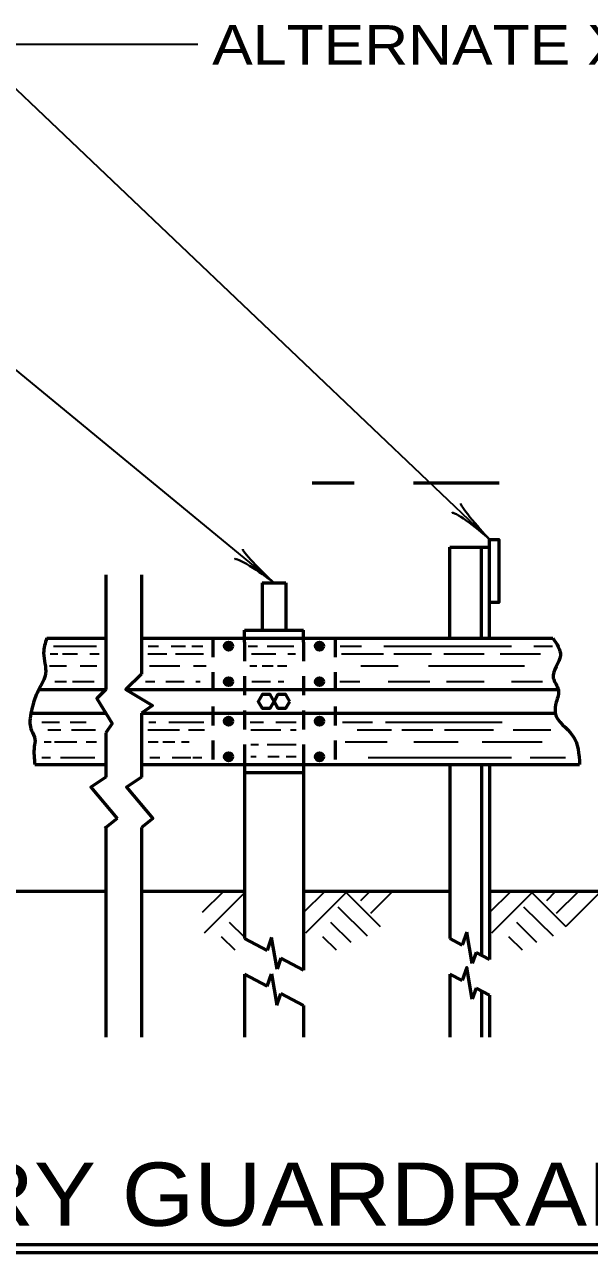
# Model space of a CAD drawing. Extents: x -60 to 620, y -42 to 398.
# Drawn here: x 228.6 to 264.3, y 75.7 to 153.4 of the extents above; entities that cross this region are included whole.
import ezdxf
from ezdxf.enums import TextEntityAlignment as Align

# ---------------------------------------------------------------- set-up
doc = ezdxf.new("R2010")
doc.units = 0
doc.header["$LTSCALE"] = 0.8
doc.linetypes.add('SHORT_DASHED', pattern=[2.7, 1.5, -1.2])
doc.layers.add('1', color=7, linetype='Continuous', lineweight=35)

msp = doc.modelspace()

# ---------------------------------------------------------------- hatches: boundary and pattern name
at = {"layer": '1'}
for points in [[(241.7638, 114.0762, 1), (241.2638, 114.0762, 1)], [(247.5138, 114.0762, 1), (247.0138, 114.0762, 1)], [(241.7638, 111.8262, 1), (241.2638, 111.8262, 1)], [(247.5138, 111.8262, 1), (247.0138, 111.8262, 1)], [(241.7638, 109.3262, 1), (241.2638, 109.3262, 1)], [(247.5138, 109.3262, 1), (247.0138, 109.3262, 1)], [(241.7638, 107.0762, 1), (241.2638, 107.0762, 1)], [(247.5138, 107.0762, 1), (247.0138, 107.0762, 1)]]:
    msp.add_hatch(color=256, dxfattribs=at).paths.add_polyline_path(points)

# ---------------------------------------------------------------- linework, layer by layer
for p, q in [((258.0138, 120.8262), (225.0642, 152.1655)), ((225.0642, 152.1655), (239.5622, 152.1655)), ((217.8122, 139.9722), (244.3888, 118.0762)), ((230.2276, 113.5762), (230.7105, 113.5762)), ((230.4346, 114.0762), (233.1596, 114.0762)), ((231.021, 113.5762), (231.9523, 113.5762)), ((232.7457, 113.5762), (233.3321, 113.5762)), ((236.4021, 113.5762), (237.6093, 113.5762)), ((236.4366, 114.0762), (237.0919, 114.0762)), ((237.8853, 114.0762), (238.7822, 114.0762)), ((238.1612, 113.5762), (239.9205, 113.5762)), ((239.1961, 114.0762), (239.886, 114.0762)), ((242.749, 114.0762), (243.3354, 114.0762)), ((242.956, 113.5762), (244.5083, 113.5762)), ((243.9563, 114.0762), (245.6465, 114.0762)), ((245.2671, 113.5762), (245.75, 113.5762)), ((248.5786, 114.0762), (249.9238, 114.0762)), ((248.6475, 113.5762), (251.3036, 113.5762)), ((251.3381, 114.0762), (259.4097, 114.0762)), ((251.959, 113.5762), (254.3391, 113.5762)), ((255.1325, 113.5762), (257.685, 113.5762)), ((258.6853, 113.5762), (261.2379, 113.5762)), ((260.824, 114.0762), (261.9968, 114.0762)), ((230.1931, 112.8262), (231.2624, 112.8262)), ((232.1248, 112.8262), (233.1941, 112.8262)), ((236.5056, 112.8262), (238.4373, 112.8262)), ((239.2996, 112.8262), (240.0929, 112.8262)), ((242.8525, 112.8262), (243.3009, 112.8262)), ((243.6458, 112.8262), (244.3357, 112.8262)), ((244.6117, 112.8262), (245.1981, 112.8262)), ((249.8893, 112.8262), (252.2349, 112.8262)), ((254.1666, 112.8262), (260.2376, 112.8262)), ((230.538, 111.8262), (231.2624, 111.8262)), ((231.6418, 111.8262), (233.0217, 111.8262)), ((236.2641, 111.8262), (236.8505, 111.8262)), ((237.5404, 111.8262), (238.7132, 111.8262)), ((239.4376, 111.8262), (239.7135, 111.8262)), ((242.9905, 111.8262), (244.1633, 111.8262)), ((244.6462, 111.8262), (245.0098, 111.8262)), ((248.5441, 111.8262), (249.8203, 111.8262)), ((251.6141, 111.8262), (254.2356, 111.8262)), ((255.3049, 111.8262), (257.685, 111.8262)), ((259.4097, 111.8262), (261.3759, 111.8262)), ((229.7102, 109.2683), (230.814, 109.2683)), ((230.0896, 108.7683), (230.9175, 108.7683)), ((231.5039, 109.2683), (232.5042, 109.2683)), ((231.5728, 108.7683), (233.0906, 108.7683)), ((236.4021, 108.7683), (238.4027, 108.7683)), ((236.4711, 109.2683), (236.9195, 109.2683)), ((237.7473, 109.2683), (239.955, 109.2683)), ((238.9892, 108.7683), (239.9895, 108.7683)), ((242.887, 109.2683), (243.7148, 109.2683)), ((242.9215, 108.7683), (244.8187, 108.7683)), ((244.5083, 109.2683), (245.7845, 109.2683)), ((245.4396, 108.7683), (245.7845, 108.7683)), ((248.7165, 109.2683), (250.6137, 109.2683)), ((249.6478, 108.7683), (251.821, 108.7683)), ((251.4416, 109.2683), (258.8233, 109.2683)), ((252.4764, 108.7683), (254.4426, 108.7683)), ((255.1669, 108.7683), (258.2714, 108.7683)), ((259.5132, 108.7683), (261.8933, 108.7683)), ((229.8482, 108.0183), (230.2966, 108.0183)), ((230.5036, 108.0183), (231.9178, 108.0183)), ((232.5042, 108.0183), (233.1596, 108.0183)), ((236.4366, 108.0183), (237.0574, 108.0183)), ((237.3679, 108.0183), (238.1267, 108.0183)), ((238.5408, 108.0183), (239.0237, 108.0183)), ((248.889, 108.0183), (251.5451, 108.0183)), ((253.2352, 108.0183), (256.0293, 108.0183)), ((257.5471, 108.0183), (261.3414, 108.0183)), ((242.9215, 107.8553), (243.4044, 107.8553)), ((243.9563, 107.8553), (245.7845, 107.8553)), ((229.7102, 107.0183), (230.2621, 107.0183)), ((230.883, 107.0183), (233.0561, 107.0183)), ((236.5401, 107.0183), (237.1609, 107.0183)), ((237.9543, 107.0183), (239.1271, 107.0183)), ((239.2651, 107.0183), (239.817, 107.0183)), ((242.9215, 107.0962), (243.2664, 107.0962)), ((243.9908, 107.0962), (244.7152, 107.0962)), ((245.1636, 107.0962), (245.7845, 107.0962)), ((250.3377, 107.0183), (259.4097, 107.0183)), ((260.5826, 107.0183), (262.8247, 107.0183)), ((241.1712, 98.5362), (239.8512, 97.2162)), ((242.5912, 98.5362), (239.9712, 95.9162)), ((247.5838, 98.5362), (246.2638, 97.2162)), ((249.0038, 98.5362), (246.3838, 95.9162)), ((248.9038, 98.5362), (251.1038, 96.3362)), ((250.4238, 98.5362), (249.8638, 97.9562)), ((251.8638, 98.5362), (250.4838, 97.1562)), ((259.3338, 98.5362), (258.0138, 97.2162)), ((260.7538, 98.5362), (258.1338, 95.9162)), ((260.6538, 98.5362), (262.8538, 96.3362)), ((262.1738, 98.5362), (261.6138, 97.9562)), ((263.6138, 98.5362), (262.2338, 97.1562)), ((265.0338, 98.5362), (262.8538, 96.3362)), ((248.4238, 97.5762), (250.2838, 95.7362)), ((260.1738, 97.5762), (262.0338, 95.7362)), ((241.5512, 96.6162), (242.5138, 95.6535)), ((247.9638, 96.6162), (249.2438, 95.3362)), ((259.7138, 96.6162), (260.9938, 95.3362)), ((241.0512, 95.6962), (241.9112, 94.8562)), ((247.4638, 95.6962), (248.3238, 94.8562)), ((259.2138, 95.6962), (260.0738, 94.8562))]:
    msp.add_line(p, q, dxfattribs=at)
at = {"layer": '1', "lineweight": 53}
for p, q in [((246.7946, 124.3998), (249.4572, 124.3998)), ((253.2072, 124.3998), (258.6239, 124.3998)), ((258.0138, 114.5762), (258.0138, 120.8262)), ((255.5138, 114.5762), (255.5138, 120.3262)), ((255.5138, 120.3262), (258.0138, 120.3262)), ((257.5138, 114.5762), (257.5138, 120.3262)), ((233.7638, 118.5762), (233.7638, 111.3262)), ((236.0138, 118.5762), (236.0138, 112.3047)), ((243.6388, 118.0762), (243.6388, 115.0762)), ((243.6388, 118.0762), (245.1388, 118.0762)), ((245.1388, 118.0762), (245.1388, 115.0762)), ((242.5138, 114.3262), (242.5138, 115.0762)), ((242.5138, 115.0762), (246.2638, 115.0762)), ((246.2638, 114.3262), (246.2638, 115.0762)), ((230.0138, 114.5762), (233.7638, 114.5762)), ((236.0138, 114.5762), (262.0138, 114.5762)), ((229.5138, 111.3262), (233.7638, 111.3262)), ((235.0138, 111.3262), (262.3698, 111.3262)), ((229.0138, 109.8262), (233.7638, 109.8262)), ((236.0138, 109.8262), (262.1778, 109.8262)), ((236.0138, 109.8262), (236.0138, 105.7827)), ((233.7638, 108.5874), (233.7638, 105.7827)), ((229.2638, 106.5762), (233.7638, 106.5762)), ((236.0138, 106.5762), (263.7138, 106.5762)), ((242.5138, 106.8262), (242.5138, 95.5762)), ((246.2638, 106.8262), (246.2638, 93.5762)), ((255.5138, 106.5762), (255.5138, 95.5762)), ((257.5138, 106.5762), (257.5138, 94.5095)), ((258.0138, 106.5762), (258.0138, 94.2428)), ((242.5138, 106.0762), (246.2638, 106.0762)), ((233.7638, 102.5893), (233.6985, 102.5348)), ((234.4665, 103.175), (233.7638, 102.5893)), ((233.7638, 102.5893), (233.7638, 89.3262)), ((236.0138, 102.5893), (236.0138, 89.3262)), ((214.7638, 98.5762), (233.7638, 98.5762)), ((236.0138, 98.5762), (242.5138, 98.5762)), ((246.2638, 98.5762), (255.5138, 98.5762)), ((258.0138, 98.5762), (278.2638, 98.5762)), ((242.5138, 95.5762), (243.9476, 94.8114)), ((244.2334, 95.6307), (243.9476, 94.8114)), ((244.5848, 93.638), (244.2334, 95.6307)), ((255.5138, 95.5762), (256.2889, 95.1628)), ((256.5747, 95.9821), (256.2889, 95.1628)), ((256.9262, 93.9893), (256.5747, 95.9821)), ((244.83, 94.3408), (244.5848, 93.638)), ((244.83, 94.3408), (246.2638, 93.5762)), ((257.1713, 94.6922), (256.9262, 93.9893)), ((257.1713, 94.6922), (258.0138, 94.2428)), ((243.9477, 92.5615), (242.5138, 93.3262)), ((242.5138, 93.3262), (242.5138, 89.3262)), ((243.9477, 92.5615), (244.2202, 93.3427)), ((244.2202, 93.3427), (244.5716, 91.35)), ((255.5138, 93.3262), (255.5138, 89.3262)), ((255.5138, 93.3262), (256.2889, 92.9128)), ((244.5716, 91.35), (244.8301, 92.0909)), ((246.2638, 91.3262), (244.8301, 92.0909)), ((257.1713, 92.4422), (256.9262, 91.7393)), ((257.1713, 92.4422), (258.0138, 91.9928)), ((257.5138, 92.2595), (257.5138, 89.3262)), ((258.0138, 91.9928), (258.0138, 89.3262)), ((246.2638, 91.3262), (246.2638, 89.3262)), ((194.8453, 76.2125), (299.5077, 76.2125)), ((194.8453, 75.7125), (299.5077, 75.7125))]:
    msp.add_line(p, q, dxfattribs=at)
at = {"layer": '1', "linetype": 'SHORT_DASHED', "lineweight": 53}
for p, q in [((240.5138, 114.5762), (240.5138, 106.5762)), ((242.5138, 114.3262), (242.5138, 106.8262)), ((246.2638, 114.3262), (246.2638, 106.8262)), ((248.2638, 114.5762), (248.2638, 106.5762))]:
    msp.add_line(p, q, dxfattribs=at)
at = {"layer": '1', "lineweight": 53}
for points in [[(258.0138, 120.8262), (258.6138, 120.8262), (258.6138, 116.8262), (258.0138, 116.8262)], [(236.0138, 112.3047), (235.0138, 111.3262), (236.7064, 110.3132), (236.0138, 109.8262)], [(233.7638, 111.3262), (233.1865, 110.7612), (234.1592, 109.1857), (233.7638, 108.5874)], [(233.7638, 105.7827), (232.8026, 105.1596), (234.4665, 103.175)], [(236.0138, 105.7827), (235.0526, 105.1596), (236.7165, 103.175), (236.0138, 102.5893)], [(256.9262, 91.7393), (256.5747, 93.7321), (256.2889, 92.9128)]]:
    msp.add_lwpolyline(points, dxfattribs=at)
for points in [[(244.3888, 110.5762), (244.1388, 111.0092), (243.6388, 111.0092), (243.3888, 110.5762), (243.6388, 110.1432), (244.1388, 110.1432)], [(245.3888, 110.5762), (245.1388, 111.0092), (244.6388, 111.0092), (244.3888, 110.5762), (244.6388, 110.1432), (245.1388, 110.1432)]]:
    msp.add_lwpolyline(points, close=True, dxfattribs=at)
for centre in [(241.5138, 114.0762), (247.2638, 114.0762), (241.5138, 111.8262), (247.2638, 111.8262), (241.5138, 109.3262), (247.2638, 109.3262), (241.5138, 107.0762), (247.2638, 107.0762)]:
    msp.add_circle(centre, 0.25, dxfattribs=at)
at = {"layer": '1', "lineweight": 40}
for centre, major_axis, ratio, start_param, end_param in [((257.3478, 121.7517), (1.1517, -1.3378), 0.07063, 3.1407148, 5.41811), ((257.3478, 121.7517), (1.1517, -1.3378), 0.07063, 3.1407148, 5.41811), ((257.0327, 121.378), (1.4015, -1.1175), 0.122415, 0.8963533, 3.1415927), ((257.0327, 121.378), (1.4015, -1.1175), 0.122415, 0.8963533, 3.1415927), ((243.371, 118.5568), (1.4775, -1.015), 0.122415, 0.8963533, 3.1415927), ((243.6586, 118.952), (1.2439, -1.2524), 0.07063, 3.1407148, 5.41811)]:
    msp.add_ellipse(centre, major_axis=major_axis, ratio=ratio, start_param=start_param, end_param=end_param, dxfattribs=at)
at = {"layer": '1', "lineweight": 53}
for points in [[(230.0138, 114.5762), (229.8224, 113.6409), (229.9404, 112.3231), (229.5138, 111.3262), (229.1539, 110.3957), (229.0138, 109.8262), (228.9573, 109.1762), (229.0556, 108.7435), (229.2719, 108.1731), (229.2326, 107.7207), (229.2638, 106.5762)], [(262.0138, 114.5762), (262.4978, 113.4821), (262.0498, 112.0737), (262.3698, 111.3262), (262.2418, 110.5373), (262.1778, 109.8262), (263.2658, 108.4246), (263.7138, 106.5762)]]:
    msp.add_spline(points, degree=3, dxfattribs=at)

# ---------------------------------------------------------------- texts
at = {"layer": '1', "width": 1.15}
msp.add_text('ALTERNATE XR-1 POST MOUNTED DELINEATOR', height=2.5, dxfattribs=at).set_placement((285.5537, 150.8628), align=Align.CENTER)
at = {"layer": '1', "width": 1.1}
msp.add_text('TEMPORARY GUARDRAIL BARRIER', height=4, dxfattribs=at).set_placement((195.8659, 77.3969))

doc.saveas('drawing.dxf')
